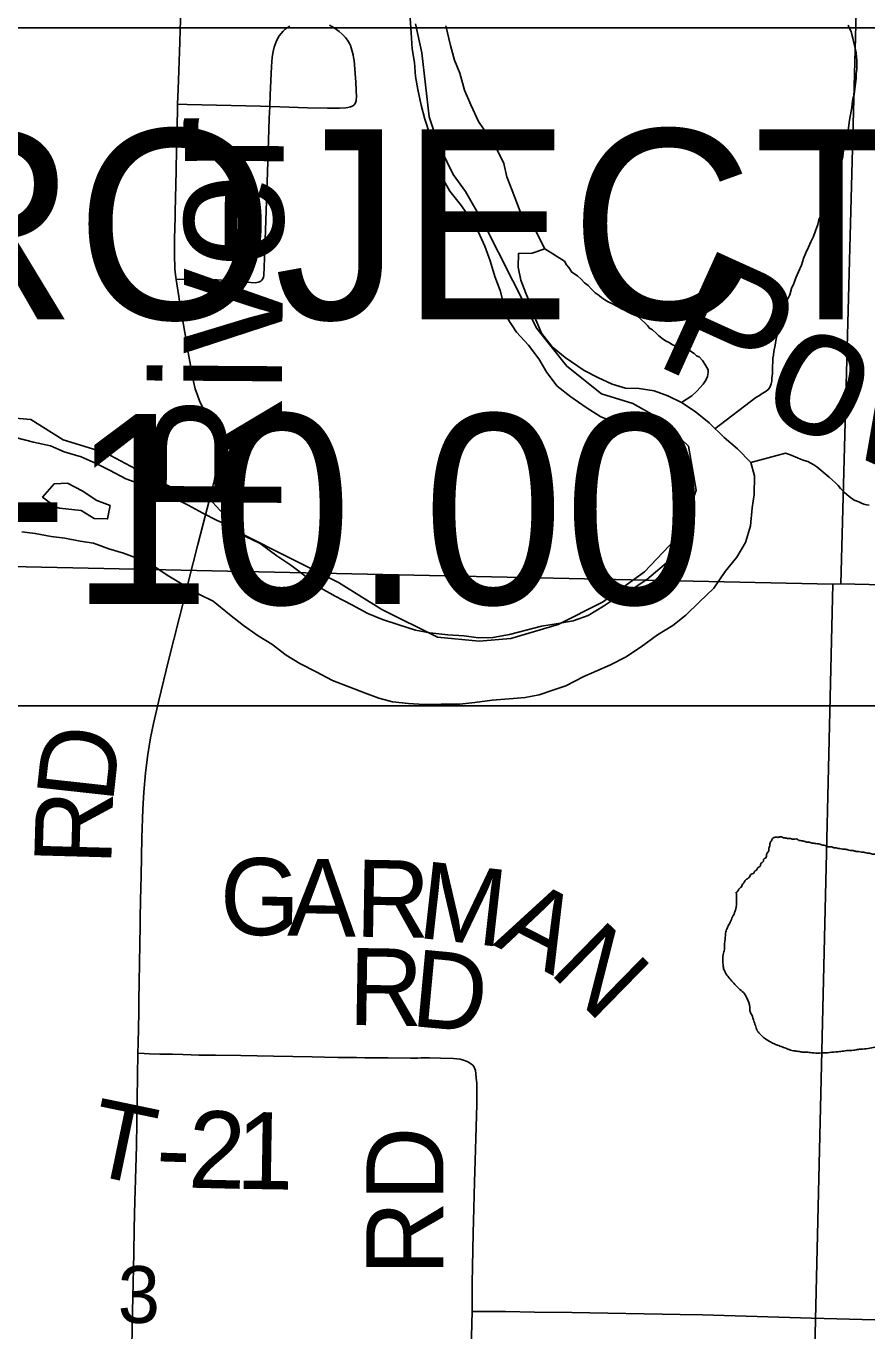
# Model space of a CAD drawing. Extents: x 0 to 34, y 0 to 22.
# Drawn here: x 4.785 to 5.405, y 15.859 to 16.822 of the extents above; entities that cross this region are included whole.
import ezdxf

# ---------------------------------------------------------------- set-up
doc = ezdxf.new("R2010")
doc.units = 0
for name, color, linetype in [('Default', 7, 'Continuous'), ('GM_X_City_Street', 7, 'Continuous'), ('GM_X_County_Road', 7, 'Continuous'), ('GM_X_County_Road_Text', 7, 'Continuous'), ('GM_X_Major_River', 7, 'Continuous'), ('GM_X_Major_River_Text', 7, 'Continuous'), ('GM_X_Minor_Lake', 7, 'Continuous'), ('GM_X_Minor_River', 7, 'Continuous'), ('GM_X_Minor_River_Text', 7, 'Continuous'), ('GM_X_Section', 7, 'Continuous'), ('GM_X_Section_Text', 7, 'Continuous'), ('GM_X_Township_Road', 7, 'Continuous'), ('GM_X_Township_Road_Text', 7, 'Continuous'), ('SH_Masking', 7, 'Continuous'), ('SH_Text', 7, 'Continuous')]:
    doc.layers.add(name, color=color, linetype=linetype)

msp = doc.modelspace()

# ---------------------------------------------------------------- linework, layer by layer
at = {"layer": 'Default'}
msp.add_lwpolyline([(4.75701, 16.53417), (4.78844, 16.53149), (4.81227, 16.51656), (4.84366, 16.50706), (4.86584, 16.49515), (4.9016, 16.47674), (4.92015, 16.47318), (4.94366, 16.44751), (5.0154, 16.41142), (5.04747, 16.3913), (5.08854, 16.3709), (5.11907, 16.36803), (5.14241, 16.37014), (5.1774, 16.38039), (5.21001, 16.39687), (5.24096, 16.41925), (5.26838, 16.4479), (5.27928, 16.47936), (5.27355, 16.51196), (5.25222, 16.53233), (5.23257, 16.54322), (5.2093, 16.5505), (5.18368, 16.5709), (5.1617, 16.5987), (5.14404, 16.63373), (5.12249, 16.67604), (5.1091, 16.6996), (5.10008, 16.71227), (5.09533, 16.72188), (5.08815, 16.73675), (5.08226, 16.75484), (5.07682, 16.80197), (5.07217, 16.82335)], dxfattribs=at)
at = {"layer": 'GM_X_City_Street'}
for points in [[(4.89568, 16.63488), (4.90243, 16.63494), (4.91423, 16.63504), (4.92602, 16.63442), (4.95389, 16.63236), (4.95516, 16.63245), (4.95621, 16.63275), (4.95714, 16.63313), (4.95803, 16.63364), (4.95888, 16.63427), (4.95941, 16.63492), (4.95989, 16.63567), (4.96023, 16.63656), (4.96043, 16.63781), (4.96053, 16.64403), (4.96107, 16.65678), (4.96304, 16.71387), (4.96441, 16.75348), (4.9647, 16.76238), (4.96499, 16.77086), (4.96591, 16.79195), (4.96653, 16.79874), (4.96732, 16.80302), (4.96799, 16.8062), (4.9694, 16.81013), (4.97038, 16.81216), (4.97167, 16.81436), (4.97314, 16.81615), (4.97461, 16.81781), (4.9762, 16.81934), (4.9776, 16.82046), (4.97952, 16.82168)], [(5.00871, 16.82238), (5.01061, 16.82137), (5.01232, 16.82035), (5.01402, 16.81915), (5.01586, 16.81764), (5.01801, 16.81574), (5.01946, 16.81442), (5.02054, 16.81315), (5.022, 16.81119), (5.02345, 16.80879), (5.02415, 16.80727), (5.02472, 16.8057), (5.0252, 16.80397), (5.02571, 16.80222), (5.02619, 16.80053), (5.02656, 16.79857), (5.02693, 16.79618), (5.02817, 16.78028), (5.02865, 16.76888), (5.02856, 16.76744), (5.02835, 16.76653), (5.0281, 16.76574), (5.02786, 16.76497), (5.0275, 16.76433), (5.0271, 16.76378), (5.02661, 16.76323), (5.02589, 16.76277)], [(4.89681, 16.76403), (4.90371, 16.76387), (4.95779, 16.76267), (4.9647, 16.76238), (4.97204, 16.76208), (4.99262, 16.76138), (5.00738, 16.76111), (5.01606, 16.76119), (5.02075, 16.76132), (5.02225, 16.76149), (5.02318, 16.76175), (5.02416, 16.762), (5.02513, 16.76239), (5.02589, 16.76277)]]:
    msp.add_lwpolyline(points, dxfattribs=at)
at = {"layer": 'GM_X_County_Road'}
for points in [[(4.89681, 16.76403), (4.8972, 16.77512), (4.8978, 16.78876), (4.89847, 16.80984), (4.89877, 16.81852), (4.899, 16.82595), (4.90007, 16.86011), (4.90119, 16.89076)], [(4.89568, 16.63488), (4.89523, 16.63827), (4.89482, 16.6426), (4.89442, 16.65313), (4.89453, 16.66509), (4.89494, 16.6805), (4.895, 16.68458), (4.89522, 16.69482), (4.89567, 16.71488), (4.89603, 16.73107), (4.89664, 16.75901), (4.89681, 16.76403)], [(4.91681, 16.53711), (4.91293, 16.5453), (4.91139, 16.5494), (4.90983, 16.55415), (4.90858, 16.55966), (4.90684, 16.56882), (4.90586, 16.57424), (4.90489, 16.57944), (4.90455, 16.5814), (4.90399, 16.58462), (4.90277, 16.59154), (4.90033, 16.60554), (4.89949, 16.61082), (4.8987, 16.61558), (4.89757, 16.62218), (4.89613, 16.63148), (4.89568, 16.63488)], [(4.92038, 16.47263), (4.92393, 16.48724), (4.92528, 16.49472), (4.92559, 16.50022), (4.92545, 16.50761), (4.92498, 16.51248), (4.92389, 16.51851), (4.92249, 16.52384), (4.92103, 16.52785), (4.91853, 16.53347), (4.91681, 16.53711)], [(4.90273, 16.40383), (4.90489, 16.41224), (4.9118, 16.43935), (4.92038, 16.47263)], [(4.86751, 16.06419), (4.86763, 16.07165), (4.86813, 16.09402), (4.86829, 16.10272), (4.86879, 16.13068), (4.86922, 16.15851), (4.8692, 16.16345), (4.86948, 16.1771), (4.8699, 16.19511), (4.87043, 16.22308), (4.8711, 16.24422), (4.87186, 16.25665), (4.87316, 16.27093), (4.87491, 16.28453), (4.87689, 16.29683), (4.87893, 16.30723), (4.88282, 16.32422), (4.89008, 16.3538), (4.89806, 16.38576), (4.90273, 16.40383)], [(4.86246, 15.81132), (4.86332, 15.86297), (4.86378, 15.88419), (4.86447, 15.91642), (4.86487, 15.93501), (4.86531, 15.95547), (4.86554, 15.96291), (4.86635, 15.99583), (4.86721, 16.04741), (4.86751, 16.06419)]]:
    msp.add_lwpolyline(points, dxfattribs=at)
at = {"layer": 'GM_X_Major_River'}
for points in [[(5.06819, 16.82741), (5.06903, 16.81676), (5.06984, 16.80497), (5.07145, 16.79468), (5.0723, 16.78441), (5.07393, 16.77488), (5.07626, 16.76344), (5.079, 16.75311), (5.08285, 16.74162), (5.08747, 16.73049), (5.09099, 16.72091), (5.09219, 16.70949), (5.09761, 16.69985), (5.1053, 16.69016), (5.1126, 16.68009), (5.11839, 16.67006), (5.12339, 16.6593), (5.12726, 16.64857), (5.13073, 16.63709), (5.13461, 16.62673), (5.137, 16.61718), (5.13937, 16.60725), (5.14664, 16.59604), (5.15547, 16.58631), (5.16315, 16.57624), (5.16894, 16.56621), (5.17662, 16.55613), (5.18663, 16.54827), (5.19817, 16.54036), (5.20897, 16.53361)], [(5.227, 16.55475), (5.21723, 16.55767), (5.20675, 16.56252), (5.19666, 16.56773), (5.18251, 16.57722), (5.17288, 16.58508), (5.1652, 16.59515), (5.16093, 16.60514), (5.15741, 16.6151), (5.15351, 16.6247), (5.14999, 16.63428), (5.14798, 16.64382), (5.14827, 16.65406), (5.15813, 16.65417), (5.16769, 16.65732), (5.16086, 16.67041), (5.15126, 16.67978), (5.1435, 16.70049), (5.13961, 16.71046), (5.13723, 16.72039), (5.13222, 16.73078), (5.12604, 16.74043), (5.11876, 16.75126), (5.11304, 16.76356), (5.10841, 16.77431), (5.10497, 16.78693), (5.10107, 16.79652), (5.09796, 16.80724), (5.09457, 16.82175)], [(4.78194, 16.44859), (4.79177, 16.44756), (4.80346, 16.44534), (4.81366, 16.44392), (4.82497, 16.44172), (4.83479, 16.44031), (4.84605, 16.4362), (4.85695, 16.43287), (4.86671, 16.42918), (4.87758, 16.42471), (4.88911, 16.41681), (4.8988, 16.41084), (4.91298, 16.40249), (4.92308, 16.39766), (4.93493, 16.38784), (4.94532, 16.37959), (4.9561, 16.37208), (4.96616, 16.36573), (4.97694, 16.35784), (4.987, 16.3515), (4.99896, 16.34548), (5.01092, 16.33908), (5.02367, 16.33417), (5.03455, 16.33008), (5.04505, 16.32599), (5.05522, 16.32344), (5.06693, 16.32198), (5.07829, 16.32128), (5.09119, 16.32169), (5.10484, 16.32169), (5.11587, 16.32291), (5.1288, 16.32445), (5.14135, 16.32562), (5.15312, 16.32643), (5.16342, 16.32843), (5.17337, 16.33195), (5.18294, 16.3351), (5.1964, 16.34194), (5.206, 16.34623), (5.21598, 16.35051), (5.22713, 16.35628), (5.23872, 16.36392), (5.25072, 16.3727), (5.26191, 16.37961), (5.2716, 16.38731), (5.28135, 16.39691), (5.29226, 16.40723), (5.30057, 16.41953), (5.3092, 16.42991), (5.31557, 16.44074), (5.31933, 16.45316), (5.32046, 16.46641), (5.32187, 16.47624), (5.32225, 16.48989), (5.3195, 16.49983), (5.30954, 16.50997), (5.29991, 16.51821), (5.28885, 16.52914), (5.27846, 16.53739), (5.26841, 16.54412), (5.25831, 16.54895), (5.24818, 16.55265), (5.23723, 16.55446), (5.227, 16.55475)], [(5.20897, 16.53361), (5.21909, 16.52954), (5.23039, 16.52657), (5.24094, 16.52438), (5.25149, 16.52182), (5.26199, 16.51773), (5.26929, 16.50767), (5.27239, 16.49658), (5.27324, 16.48631), (5.27479, 16.47412), (5.27262, 16.46431), (5.26851, 16.45266), (5.26553, 16.44098), (5.26219, 16.43007), (5.25247, 16.42161), (5.24277, 16.41353), (5.23272, 16.40697), (5.22118, 16.40084), (5.21075, 16.39391), (5.19956, 16.38701), (5.18846, 16.38314), (5.1774, 16.38117), (5.16522, 16.37923), (5.14154, 16.37305), (5.12934, 16.37073), (5.11872, 16.37064), (5.10814, 16.37207), (5.09603, 16.37279), (5.0828, 16.37429), (5.07224, 16.37609), (5.05908, 16.38025), (5.04781, 16.38398), (5.03694, 16.38845), (5.02537, 16.39484), (5.01304, 16.40125), (5.00296, 16.40684), (4.99331, 16.41432), (4.98031, 16.42416), (4.96989, 16.4309), (4.95763, 16.43997), (4.94678, 16.4452), (4.93674, 16.4523), (4.92588, 16.45716), (4.91541, 16.46238), (4.90458, 16.46837), (4.89337, 16.47399), (4.88364, 16.47881), (4.87275, 16.48252), (4.85849, 16.48785), (4.84654, 16.49425), (4.83682, 16.49907), (4.82558, 16.50394), (4.81317, 16.50769), (4.80306, 16.51214), (4.79062, 16.51476), (4.77632, 16.51857)], [(4.82561, 16.46447), (4.8353, 16.45851), (4.84515, 16.45824), (4.84694, 16.46806), (4.83719, 16.47174), (4.82639, 16.47887), (4.81556, 16.48448), (4.80568, 16.48399), (4.79707, 16.47436), (4.8071, 16.46688), (4.80973, 16.46604)], [(4.80973, 16.46604), (4.82561, 16.46447)]]:
    msp.add_lwpolyline(points, dxfattribs=at)
at = {"layer": 'GM_X_Minor_Lake'}
for points in [[(5.55234, 16.24213), (5.55123, 16.2433), (5.5501, 16.24371), (5.5486, 16.2445), (5.54748, 16.24529), (5.54635, 16.2457), (5.54523, 16.24648), (5.54373, 16.2469), (5.54261, 16.24769), (5.54035, 16.2485), (5.53923, 16.24929), (5.5381, 16.2497), (5.53697, 16.24972), (5.53584, 16.25013), (5.53472, 16.25092), (5.53358, 16.25094), (5.53245, 16.25135), (5.52904, 16.25144), (5.52445, 16.25003), (5.52331, 16.25006), (5.52176, 16.24895), (5.51947, 16.24825), (5.51484, 16.24533), (5.5137, 16.24498), (5.51254, 16.24425), (5.51061, 16.24316), (5.50947, 16.2428), (5.50793, 16.24208), (5.5045, 16.24141), (5.50334, 16.24067), (5.50219, 16.24032), (5.50103, 16.23921), (5.49873, 16.23851), (5.49795, 16.23739), (5.4964, 16.23629), (5.49523, 16.23518), (5.49366, 16.23294), (5.49173, 16.23185), (5.49133, 16.23072), (5.48978, 16.22962), (5.4886, 16.22813), (5.48631, 16.22742), (5.48361, 16.22559), (5.48207, 16.22487), (5.47748, 16.22347), (5.47635, 16.22349), (5.47481, 16.22277), (5.47328, 16.22243), (5.46755, 16.22067), (5.46639, 16.21994), (5.46486, 16.2196), (5.46371, 16.21887), (5.46216, 16.21777), (5.46101, 16.21742), (5.45985, 16.21631), (5.45831, 16.21558), (5.45715, 16.21485), (5.4556, 16.21337), (5.45443, 16.21226), (5.45328, 16.21153), (5.45211, 16.21042), (5.45095, 16.20969), (5.44978, 16.20858), (5.44747, 16.20712), (5.44517, 16.20604), (5.44364, 16.20569), (5.43681, 16.20586), (5.4334, 16.20595), (5.43227, 16.20635), (5.4281, 16.20645), (5.42207, 16.20812), (5.42093, 16.20815), (5.41866, 16.20858), (5.41679, 16.20939), (5.41301, 16.21024), (5.41038, 16.21106), (5.40924, 16.21109), (5.40773, 16.21151), (5.40433, 16.21197), (5.40282, 16.21239), (5.4013, 16.21242), (5.39903, 16.21286), (5.39714, 16.21291), (5.39601, 16.21331), (5.39374, 16.21375), (5.3926, 16.21377), (5.3911, 16.21419), (5.38845, 16.21463), (5.38731, 16.21466), (5.38505, 16.2151), (5.38391, 16.21513), (5.3824, 16.21554), (5.38126, 16.21557), (5.38014, 16.21598), (5.37825, 16.21641), (5.37635, 16.21645), (5.37522, 16.21686)], [(5.37522, 16.21686), (5.37335, 16.21766), (5.37221, 16.21769), (5.37108, 16.2181), (5.36957, 16.21851), (5.36843, 16.21854), (5.36655, 16.21897), (5.36541, 16.219), (5.3639, 16.21941), (5.36277, 16.21982), (5.36164, 16.21985), (5.3605, 16.21988), (5.35862, 16.22068), (5.35748, 16.22071), (5.35597, 16.22113), (5.35484, 16.22115), (5.35372, 16.22194), (5.34992, 16.22203), (5.3488, 16.22244), (5.34652, 16.22249), (5.34539, 16.2229), (5.34425, 16.22293), (5.34313, 16.22334), (5.342, 16.22374), (5.34086, 16.22377), (5.33971, 16.22342), (5.33743, 16.22348), (5.33512, 16.22202), (5.33471, 16.22089), (5.33393, 16.21977), (5.33352, 16.21864), (5.33348, 16.21712), (5.33267, 16.21486), (5.33263, 16.21334), (5.33145, 16.21185), (5.33104, 16.21073), (5.33102, 16.20959), (5.33022, 16.20809), (5.32906, 16.20736), (5.32864, 16.20547), (5.32709, 16.20437), (5.32628, 16.20211), (5.32473, 16.20101), (5.32355, 16.19914), (5.322, 16.19804), (5.32159, 16.19691), (5.32044, 16.19656), (5.31849, 16.19433), (5.31694, 16.19285), (5.31578, 16.19212), (5.31421, 16.18988), (5.31303, 16.18839), (5.31261, 16.18688), (5.31107, 16.18578), (5.31028, 16.18466), (5.30948, 16.18316), (5.30869, 16.18292)], [(5.30869, 16.18292), (5.30837, 16.17054), (5.30754, 16.1679), (5.30553, 16.16377), (5.30391, 16.16002), (5.30231, 16.15702), (5.30108, 16.15363), (5.3006, 16.14984), (5.30004, 16.1434), (5.29997, 16.14074), (5.29911, 16.13696), (5.29895, 16.1305), (5.29925, 16.12745), (5.30031, 16.12438), (5.3025, 16.12091), (5.30544, 16.11741), (5.31136, 16.11117), (5.31471, 16.10804), (5.31653, 16.10495), (5.31863, 16.09805), (5.31893, 16.095), (5.32037, 16.09192), (5.32143, 16.08885), (5.32284, 16.08463), (5.32426, 16.0808), (5.32684, 16.07769), (5.32944, 16.07534), (5.33318, 16.07296), (5.33618, 16.07135), (5.33919, 16.07013), (5.34258, 16.0689), (5.34672, 16.06727), (5.35087, 16.06602), (5.35466, 16.06554), (5.35731, 16.06509), (5.36035, 16.06501), (5.36452, 16.06452), (5.37022, 16.06436), (5.37594, 16.06459), (5.38204, 16.06519), (5.38585, 16.06547), (5.39005, 16.06611), (5.39538, 16.06635), (5.39882, 16.06702), (5.40187, 16.06731), (5.40721, 16.06793), (5.41218, 16.06894), (5.4206, 16.07062), (5.43017, 16.07302), (5.4367, 16.07551), (5.44437, 16.07796), (5.45089, 16.08007), (5.45585, 16.08069), (5.46006, 16.08134), (5.46615, 16.08156), (5.47035, 16.08221), (5.4734, 16.0825), (5.47872, 16.08236), (5.48137, 16.08191), (5.4844, 16.08145), (5.48742, 16.08061), (5.49271, 16.07933), (5.50063, 16.07684), (5.50364, 16.07561), (5.50779, 16.07436), (5.51117, 16.07237), (5.51492, 16.07037), (5.5179, 16.06801), (5.52314, 16.06483), (5.52615, 16.06361), (5.52917, 16.06277), (5.53368, 16.06075), (5.54006, 16.05754), (5.5427, 16.0567), (5.54377, 16.05402), (5.54557, 16.05016), (5.54841, 16.04249), (5.54979, 16.03713), (5.55042, 16.03217), (5.54995, 16.02876), (5.54796, 16.0254), (5.54248, 16.01946), (5.54125, 16.01608), (5.54155, 16.01303), (5.54298, 16.00957), (5.54555, 16.00608), (5.54892, 16.00409), (5.55304, 16.0017), (5.55568, 16.00087), (5.5587, 16.00002), (5.56248, 15.99916), (5.56627, 15.99868), (5.56969, 15.99859), (5.57389, 15.99886), (5.57847, 15.99988), (5.58346, 16.00126), (5.58658, 16.00422)]]:
    msp.add_spline(points, degree=3, dxfattribs=at)
at = {"layer": 'GM_X_Minor_River'}
for points in [[(5.39118, 16.82224), (5.39226, 16.81994), (5.39334, 16.81763), (5.39404, 16.81533), (5.39474, 16.81266), (5.39541, 16.80922), (5.39646, 16.8054), (5.39713, 16.80196), (5.39743, 16.79891), (5.39775, 16.79625), (5.39766, 16.79283), (5.39758, 16.7898), (5.39712, 16.78639), (5.39703, 16.78297), (5.39656, 16.77919), (5.39608, 16.7754), (5.3956, 16.77123), (5.39476, 16.76784), (5.39429, 16.76443), (5.39383, 16.7614), (5.39251, 16.75384), (5.39204, 16.75043), (5.39156, 16.74627), (5.39071, 16.74287), (5.39025, 16.73946), (5.38979, 16.73644), (5.38897, 16.7338), (5.38813, 16.73078), (5.38768, 16.72813), (5.38723, 16.72511), (5.38639, 16.72209), (5.38556, 16.71907), (5.38473, 16.71644), (5.38388, 16.71266), (5.38185, 16.70739), (5.37981, 16.70175), (5.37739, 16.69611), (5.37536, 16.69084), (5.37335, 16.68672), (5.37176, 16.68372), (5.37055, 16.68109)], [(5.37055, 16.68109), (5.36974, 16.67883), (5.36889, 16.67544), (5.36725, 16.67054), (5.36563, 16.6664), (5.36364, 16.66265), (5.36201, 16.65852), (5.36001, 16.65439), (5.35839, 16.65025), (5.35675, 16.64536), (5.35472, 16.64047), (5.35271, 16.63596), (5.35109, 16.63183), (5.34948, 16.62807), (5.34822, 16.62354), (5.34622, 16.61942), (5.345, 16.61603), (5.34417, 16.61339), (5.34335, 16.61113), (5.34253, 16.6085), (5.34168, 16.6051), (5.34044, 16.60095), (5.33958, 16.5968), (5.33872, 16.59302), (5.33788, 16.58962), (5.33741, 16.58622), (5.33654, 16.58168), (5.33609, 16.57903), (5.33566, 16.57677), (5.33561, 16.57487), (5.33548, 16.56993), (5.33543, 16.56766), (5.33537, 16.56538), (5.33491, 16.56197), (5.33485, 16.55969), (5.33442, 16.55781), (5.3336, 16.55517), (5.33203, 16.55331), (5.3301, 16.55184), (5.32779, 16.55076), (5.32585, 16.54929), (5.32316, 16.54784), (5.29287, 16.52456)], [(5.16769, 16.65732), (5.18208, 16.64826), (5.18353, 16.64557), (5.18539, 16.64362), (5.18758, 16.64015), (5.19169, 16.63738), (5.19429, 16.63504), (5.19688, 16.63231), (5.19949, 16.63035), (5.20208, 16.62763), (5.20467, 16.6249), (5.20766, 16.62292), (5.20952, 16.62136), (5.21176, 16.61978), (5.21438, 16.6182), (5.21701, 16.61699), (5.22076, 16.615), (5.2245, 16.613), (5.22827, 16.61177), (5.23053, 16.61095), (5.23241, 16.61014), (5.23689, 16.60699), (5.23874, 16.60505), (5.24134, 16.6027), (5.24319, 16.60076), (5.24466, 16.59882), (5.24691, 16.59762), (5.24988, 16.59489), (5.25174, 16.59332), (5.25509, 16.59058), (5.25696, 16.58939), (5.25921, 16.5882), (5.26183, 16.58661), (5.26522, 16.58538), (5.26711, 16.58496), (5.2705, 16.58373), (5.27237, 16.58293), (5.27426, 16.5825), (5.27762, 16.58013), (5.27948, 16.57857), (5.28136, 16.57776), (5.28395, 16.57504), (5.28614, 16.57156), (5.28796, 16.5681), (5.28791, 16.5662), (5.28745, 16.56317), (5.28625, 16.56054), (5.28428, 16.55756), (5.27959, 16.55236), (5.27608, 16.54903), (5.26841, 16.54412)], [(5.3195, 16.49983), (5.34492, 16.50664), (5.34794, 16.50581), (5.35094, 16.50459), (5.35395, 16.50338), (5.3562, 16.50218), (5.35884, 16.50135), (5.36148, 16.50053), (5.36373, 16.49933), (5.36598, 16.49813), (5.36822, 16.49656), (5.37715, 16.48911), (5.37975, 16.48677), (5.38198, 16.48481), (5.38383, 16.48287), (5.38567, 16.48054), (5.38864, 16.47781), (5.39198, 16.47469), (5.39571, 16.47193), (5.3991, 16.47071), (5.40098, 16.4699), (5.40286, 16.46909), (5.40475, 16.46867), (5.40663, 16.46824)]]:
    msp.add_lwpolyline(points, dxfattribs=at)
at = {"layer": 'GM_X_Section'}
for points in [[(4.41097, 17.43188), (5.41251, 17.40958), (5.38574, 16.41038), (5.38005, 16.41012), (4.38456, 16.43152)], [(5.41251, 17.40958), (6.41184, 17.39355), (6.38559, 16.38675), (5.38574, 16.41038)], [(4.38456, 16.43152), (5.38005, 16.41012), (5.35524, 15.36699), (4.35758, 15.39266)], [(5.38005, 16.41012), (5.38574, 16.41038), (6.38559, 16.38675), (6.36308, 15.34539), (5.35524, 15.36699)]]:
    msp.add_lwpolyline(points, close=True, dxfattribs=at)
at = {"layer": 'GM_X_Township_Road'}
for points in [[(4.86751, 16.06419), (4.8721, 16.06397), (4.87571, 16.06379), (4.88376, 16.06362), (4.89306, 16.06342), (4.90053, 16.06323), (4.90674, 16.06307), (4.91231, 16.06284), (4.916, 16.06281), (4.9246, 16.06273), (4.9433, 16.06241), (4.96747, 16.06198), (4.99598, 16.06151), (5.0051, 16.06128), (5.01497, 16.06105), (5.0287, 16.06093), (5.03493, 16.06088), (5.05206, 16.06079), (5.06844, 16.06065), (5.0715, 16.06064), (5.07396, 16.06064), (5.07642, 16.0607), (5.08254, 16.0607), (5.0907, 16.06051), (5.10015, 16.06027), (5.10508, 16.05977), (5.1075, 16.05918), (5.11036, 16.05807), (5.1119, 16.05717), (5.11271, 16.0567), (5.1137, 16.05594), (5.11455, 16.0553)], [(5.11398, 15.87372), (5.11399, 15.89438), (5.11475, 15.93144), (5.11519, 15.94966), (5.11566, 15.96931), (5.11628, 15.98483), (5.11678, 16.00164), (5.11751, 16.02647), (5.11732, 16.04176), (5.11705, 16.04604), (5.11671, 16.04933), (5.11633, 16.05135), (5.11599, 16.05265), (5.11541, 16.05395), (5.11455, 16.0553)], [(5.10565, 15.37339), (5.10574, 15.3812), (5.10593, 15.39985), (5.10611, 15.41664), (5.10664, 15.45331), (5.10714, 15.5074), (5.10745, 15.53786), (5.10765, 15.55651), (5.10794, 15.57082), (5.10814, 15.58138), (5.10828, 15.58511), (5.10862, 15.61992), (5.10879, 15.62613), (5.10939, 15.65533), (5.10998, 15.68579), (5.11088, 15.73363), (5.11123, 15.7541), (5.11134, 15.76641), (5.11198, 15.79865), (5.11236, 15.81723), (5.11272, 15.82958), (5.11344, 15.85502), (5.1138, 15.86464), (5.11398, 15.87372)], [(5.11398, 15.87372), (5.12171, 15.8738), (5.13854, 15.87364), (5.16003, 15.87332), (5.18751, 15.87292), (5.26745, 15.87152), (5.28376, 15.87129), (5.36433, 15.86892), (5.42013, 15.86728), (5.44345, 15.86691), (5.47126, 15.86674), (5.53574, 15.86613), (5.57357, 15.86485), (5.59886, 15.864), (5.60878, 15.86366)]]:
    msp.add_lwpolyline(points, dxfattribs=at)
at = {"layer": 'SH_Masking'}
msp.add_lwpolyline([(3.85754, 16.82046), (5.60206, 16.82046), (5.60206, 16.32046), (3.85754, 16.32046)], close=True, dxfattribs=at)
at = {"layer": 'SH_Text'}
msp.add_lwpolyline([(3.85754, 16.32046), (5.60206, 16.32046), (5.60206, 16.82046), (3.85754, 16.82046)], close=True, dxfattribs=at)

# ---------------------------------------------------------------- texts
at = {"layer": 'GM_X_County_Road_Text'}
for s, rotation, p in [('D', 83.67971, (4.84899, 16.24775)), ('R', 88.42499, (4.84779, 16.20234))]:
    msp.add_text(s, height=0.05682, rotation=rotation, dxfattribs=at).set_placement(p)
at = {"layer": 'GM_X_Major_River_Text'}
msp.add_text('River', height=0.094758, rotation=89.60693, dxfattribs=at).set_placement((4.97312, 16.45966))
at = {"layer": 'GM_X_Minor_River_Text'}
msp.add_text('Powell', height=0.094746, rotation=335.62049, dxfattribs=at).set_placement((5.24605, 16.57308))
at = {"layer": 'GM_X_Section_Text'}
msp.add_text('3', height=0.04186, rotation=0.00001, dxfattribs=at).set_placement((4.85264, 15.86532))
at = {"layer": 'GM_X_Township_Road_Text'}
for s, height, rotation, p in [('G', 0.05682, 359.07469, (4.92756, 16.15178)), ('A', 0.05682, 359.07105, (4.97755, 16.15097)), ('R', 0.05682, 359.05543, (5.02754, 16.15016)), ('M', 0.05682, 353.60403, (5.07277, 16.14948)), ('A', 0.05682, 333.02361, (5.12892, 16.14415)), ('N', 0.05682, 315.6195, (5.16978, 16.12412)), ('R', 0.05682, 359.07495, (5.02246, 16.08509)), ('D', 0.05682, 354.69591, (5.06797, 16.0844)), ('T', 0.05682, 348.23031, (4.82804, 15.97577)), ('2', 0.05682, 358.64501, (4.90414, 15.96509)), ('1', 0.05682, 359.11427, (4.93964, 15.96425)), ('RD', 0.056818, 90, (5.0928, 15.90026)), ('-', 0.05682, 358.2209, (4.88036, 15.96583))]:
    msp.add_text(s, height=height, rotation=rotation, dxfattribs=at).set_placement(p)
at = {"layer": 'SH_Text'}
for s, p in [('BEGIN PROJECT', (3.92754, 16.60546)), ('STA. 224+10.00', (3.92754, 16.39546))]:
    msp.add_text(s, height=0.1399997, dxfattribs=at).set_placement(p)

doc.saveas('drawing.dxf')
